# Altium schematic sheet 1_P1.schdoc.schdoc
size 309 x 223 mm; Symbol: Sheet-Symbol_A4; Device: Sheet-Symbol_A4; @Project Name: Microplate-Reader-V1.0; @Page Count: 1; @Update Date: 2024-02-06; @Create Date: 2024-02-05; @Schematic Name: Schematic2; @Page No: 1; @Page Name: P1; Company: EasyEDA.com; Reviewed: EasyEDA; Version: V0.1; Page Size: A4; Part Number: JLCPCB-002; Drawn: EasyEDA
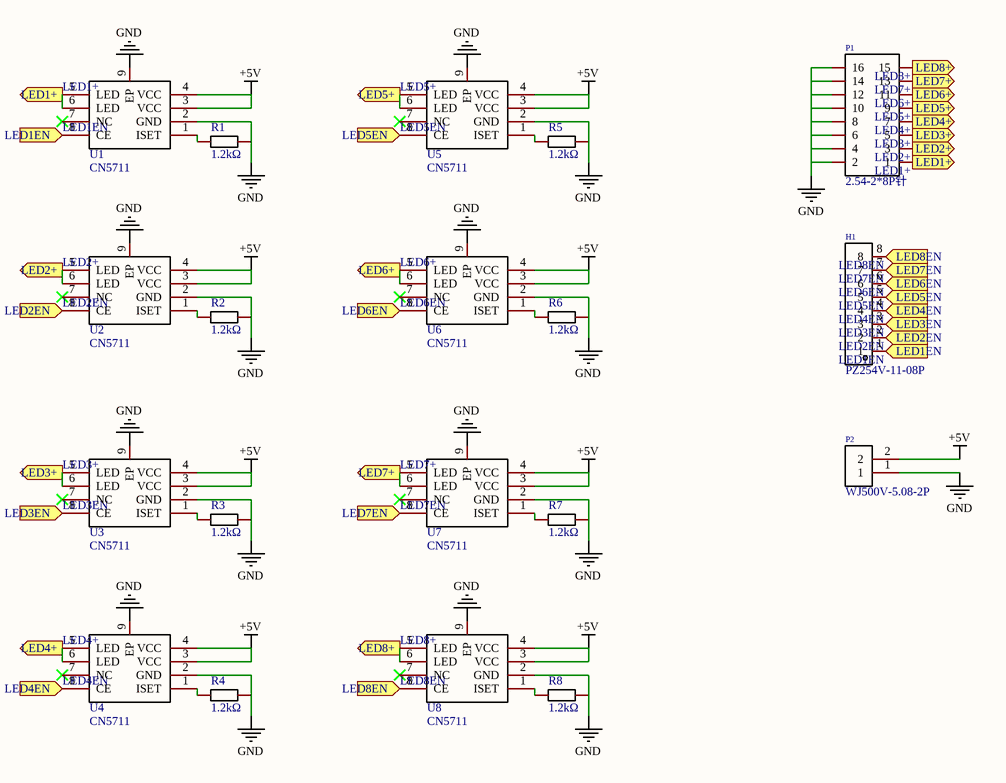
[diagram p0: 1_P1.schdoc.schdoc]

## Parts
H1  PZ254V-11-08P  [HDR-TH_8P-P2.54-V-M]
P1  2.54-2*8P针  [HDR-TH_16P-P2.54-V-M-R2-C8-S2.54]
P2  WJ500V-5.08-2P  [CONN-TH_2P-P5.00_WJ500V-5.08-2P]
R1  1.2kΩ  [R0603]
R2  1.2kΩ  [R0603]
R3  1.2kΩ  [R0603]
R4  1.2kΩ  [R0603]
R5  1.2kΩ  [R0603]
R6  1.2kΩ  [R0603]
R7  1.2kΩ  [R0603]
R8  1.2kΩ  [R0603]
U1  CN5711  [SOIC-8_L5.0-W4.0-P1.27-LS6.0-BL-EP2.0]
U2  CN5711  [SOIC-8_L5.0-W4.0-P1.27-LS6.0-BL-EP2.0]
U3  CN5711  [SOIC-8_L5.0-W4.0-P1.27-LS6.0-BL-EP2.0]
U4  CN5711  [SOIC-8_L5.0-W4.0-P1.27-LS6.0-BL-EP2.0]
U5  CN5711  [SOIC-8_L5.0-W4.0-P1.27-LS6.0-BL-EP2.0]
U6  CN5711  [SOIC-8_L5.0-W4.0-P1.27-LS6.0-BL-EP2.0]
U7  CN5711  [SOIC-8_L5.0-W4.0-P1.27-LS6.0-BL-EP2.0]
U8  CN5711  [SOIC-8_L5.0-W4.0-P1.27-LS6.0-BL-EP2.0]

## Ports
LED1+ (out), LED1EN (in), LED2+ (out), LED2EN (in), LED3+ (out), LED3EN (in), LED4+ (out), LED4EN (in), LED5+ (out), LED5EN (in), LED6+ (out), LED6EN (in), LED7+ (out), LED7EN (in), LED8+ (out), LED8EN (in)

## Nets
+5V: P2.2 U1.3(VCC) U1.4(VCC) U2.3(VCC) U2.4(VCC) U3.3(VCC) U3.4(VCC) U4.3(VCC) U4.4(VCC) U5.3(VCC) U5.4(VCC) U6.3(VCC) U6.4(VCC) U7.3(VCC) U7.4(VCC) U8.3(VCC) U8.4(VCC)
GND: P1.2 P1.4 P1.6 P1.8 P1.10 P1.12 P1.14 P1.16 P2.1 R1.2 R2.2 R3.2 R4.2 R5.2 R6.2 R7.2 R8.2 U1.2(GND) U1.9(EP) U2.2(GND) U2.9(EP) U3.2(GND) U3.9(EP) U4.2(GND) U4.9(EP) U5.2(GND) U5.9(EP) U6.2(GND) U6.9(EP) U7.2(GND) U7.9(EP) U8.2(GND) U8.9(EP)
LED1+: P1.1 U1.5(LED) U1.6(LED) ; port LED1+
LED1EN: H1.1 U1.8(CE) ; port LED1EN
LED2+: P1.3 U2.5(LED) U2.6(LED) ; port LED2+
LED2EN: H1.2 U2.8(CE) ; port LED2EN
LED3+: P1.5 U3.5(LED) U3.6(LED) ; port LED3+
LED3EN: H1.3 U3.8(CE) ; port LED3EN
LED4+: P1.7 U4.5(LED) U4.6(LED) ; port LED4+
LED4EN: H1.4 U4.8(CE) ; port LED4EN
LED5+: P1.9 U5.5(LED) U5.6(LED) ; port LED5+
LED5EN: H1.5 U5.8(CE) ; port LED5EN
LED6+: P1.11 U6.5(LED) U6.6(LED) ; port LED6+
LED6EN: H1.6 U6.8(CE) ; port LED6EN
LED7+: P1.13 U7.5(LED) U7.6(LED) ; port LED7+
LED7EN: H1.7 U7.8(CE) ; port LED7EN
LED8+: P1.15 U8.5(LED) U8.6(LED) ; port LED8+
LED8EN: H1.8 U8.8(CE) ; port LED8EN
NetR1_1: R1.1 U1.1(ISET)
NetR2_1: R2.1 U2.1(ISET)
NetR3_1: R3.1 U3.1(ISET)
NetR4_1: R4.1 U4.1(ISET)
NetR5_1: R5.1 U5.1(ISET)
NetR6_1: R6.1 U6.1(ISET)
NetR7_1: R7.1 U7.1(ISET)
NetR8_1: R8.1 U8.1(ISET)

Not connected (* = marked no-connect by the designer): U1 7(NC)*; U2 7(NC)*; U3 7(NC)*; U4 7(NC)*; U5 7(NC)*; U6 7(NC)*; U7 7(NC)*; U8 7(NC)*

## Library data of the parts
H1 = PZ254V-11-08P: Manufacturer: XFCN(兴飞); Add into BOM: yes; Pin Structure: 1x8P; Pitch: 2.54mm; Circluar Pins/Square Pins: Square Pins; Description: Pin Structure:1x8P Pitch:2.54mm Row Spacing:- Circluar Pins/Square Pins:Square Pins Mounting Type:Straight Number of Rows:Plugin Number of Pins:8P Current Rating (Max):- Voltage Rating (Max):- Length of Mating Pin:6mm Insulation Height:2.5mm Length of End
P1 = 2.54-2*8P针_C68234: Manufacturer: BOOMELE(博穆精密); Symbol: Header-Male-2.54_2x8; Add into BOM: yes; Pin Structure: 2x8P; Pitch: 2.54mm; Circluar Pins/Square Pins: Square Pins; Description: Pin Structure:2x8P Pitch:2.54mm Row Spacing:2.54mm Circluar Pins/Square Pins:Square Pins Mounting Type:Straight Number of Rows:双排 Number of Pins:16P Current Rating (Max):- Voltage Rating (Max):- Length of Mating Pin:5.9mm Insulation Height:2.54mm Length o
P2 = WJ500V-5.08-2P: Manufacturer: KANGNEX(康奈克斯电气); Symbol: WJ500V-5.08-2P-14-00A; Add into BOM: yes; Structure: 1x2P; Pitch: 5.08mm; Current Rating (Max): 18A; Voltage Rating (Max): 250V; Wire Gauge - AWG: 14~30; Wire Gauge - mm2: 2.5; Number of PINs Per Row: 2; Description: Structure:1x2P Pitch:5.08mm Color:Green Mounting Style:Straight Current Rating (Max):18A Voltage Rating (Max):250V Number of Pins:2P Number of Rows:1 Wire Gauge - AWG:14~30 Wire Gauge - AWG:14~30 Wire Gauge - mm2:2.5 Wire Gauge - mm2:2.5 Number of PINs Pe
R1-R8 = CR0603J1K20P05Z: Type:Thick Film Resistors Resistance: Tolerance:±5% Tolerance:±5% Power(Watts): Temperature Coefficient:±100ppm/℃ Temperature Coefficient:±100ppm/℃ Operating Temperature Range:-55℃~+155℃ Operating Temperature Range:-55℃~+155℃; Manufacturer: EVER OHMS(天二科技); Symbol: Res; Add into BOM: yes; Tolerance: ±5%
U1-U8 = CN5711: Manufacturer: CONSONANCE(上海如韵); Add into BOM: yes; Input Voltage: 2.8V~6V; Description: Type:- Input Voltage:2.8V~6V Input Voltage:2.8V~6V Switch Frequency:- Switch Frequency:- Channels:- Output Voltage:- Output Voltage:- Dimming:- Features:- Topology:- Operating temperature:- Operating temperature:-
